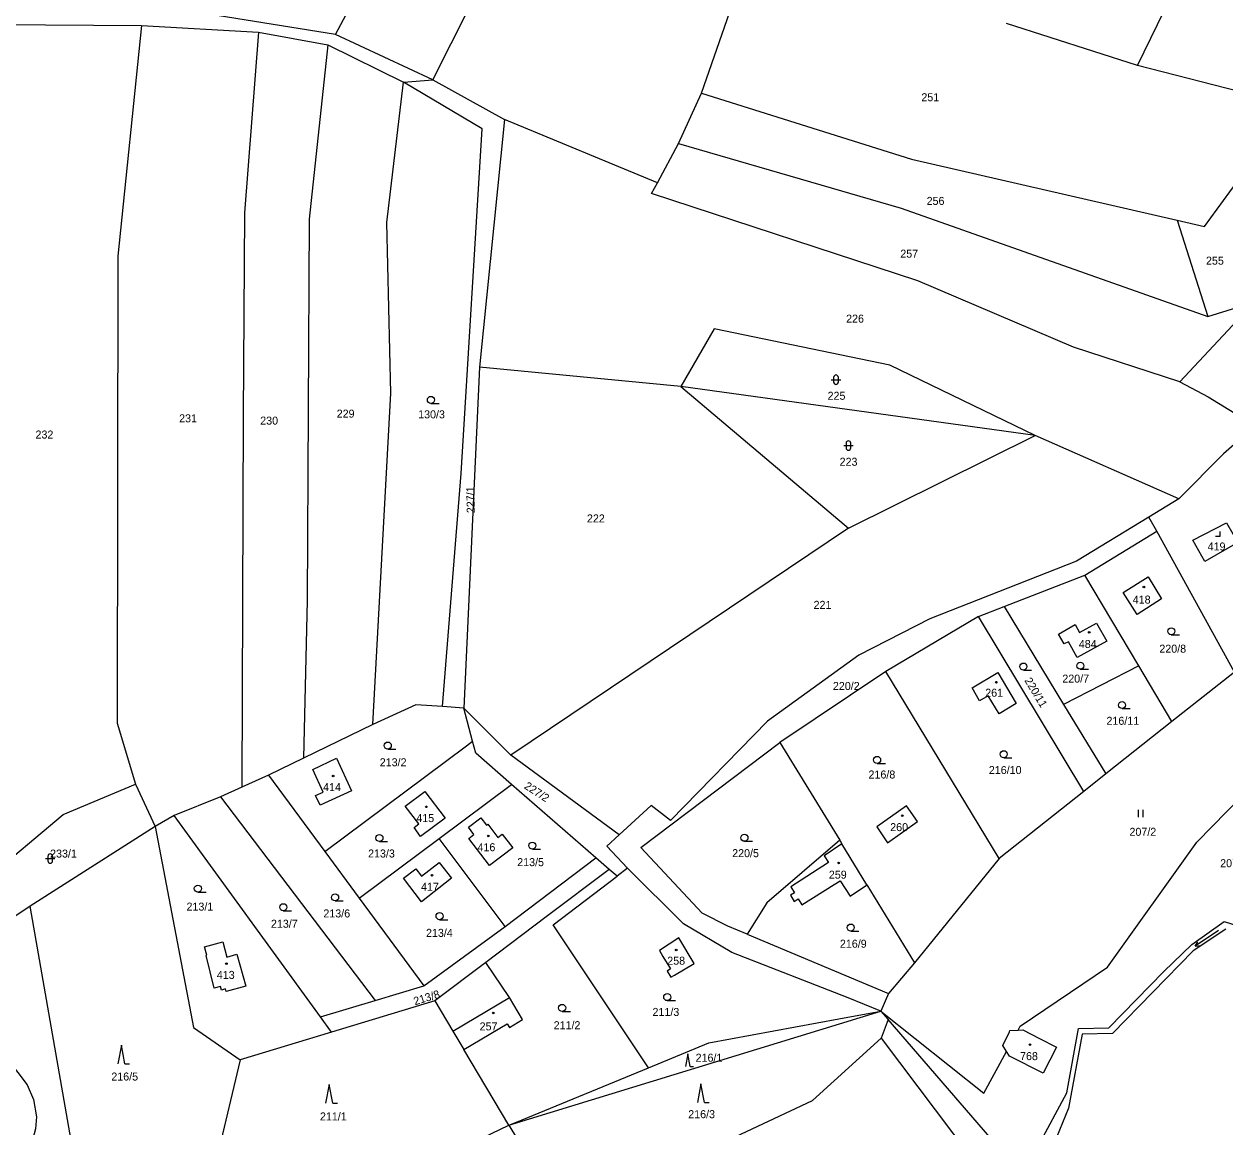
# Model space of a CAD drawing. Extents: x -725728 to -720881, y -1068679 to -1063504.
# Drawn here: x -722267.5 to -722012.3, y -1065928.4 to -1065694 of the extents above; entities that cross this region are included whole.
import ezdxf

# ---------------------------------------------------------------- set-up
doc = ezdxf.new("R2010")
doc.units = 0
for name, color, linetype in [('Hranice parcel', 7, 'Continuous'), ('Parcelní čísla', 7, 'Continuous'), ('Vnitřní kresba', 7, 'Continuous'), ('Značky budov', 7, 'Continuous'), ('Značky kultur', 7, 'Continuous')]:
    doc.layers.add(name, color=color, linetype=linetype)

# ---------------------------------------------------------------- blocks, each defined once
blk = doc.blocks.new('4.02_3')
at = {"layer": 'Značky budov'}
blk.add_circle((-0.001, 0), 0.0175, dxfattribs=at)
blk = doc.blocks.new('4.02_4')
at = {"layer": 'Značky budov'}
blk.add_circle((-0.001, 0), 0.0175, dxfattribs=at)
blk = doc.blocks.new('3.08_1')
at = {"layer": 'Značky kultur'}
for p, q in [((0, 0.4), (-0.075, 0)), ((0.075, 0), (0, 0.4)), ((0.075, 0), (0.175, 0))]:
    blk.add_line(p, q, dxfattribs=at)
blk = doc.blocks.new('3.04_2')
at = {"layer": 'Značky kultur'}
blk.add_line((0.001, 0), (0.176, 0), dxfattribs=at)
blk.add_circle((0.001, 0.075), 0.075, dxfattribs=at)
blk = doc.blocks.new('3.04_3')
at = {"layer": 'Značky kultur'}
blk.add_line((0.001, 0), (0.176, 0), dxfattribs=at)
blk.add_circle((0.001, 0.075), 0.075, dxfattribs=at)
blk = doc.blocks.new('3.06_1')
at = {"layer": 'Značky kultur'}
for p, q in [((-0.051, 0), (-0.051, 0.15)), ((0.049, 0), (0.049, 0.15))]:
    blk.add_line(p, q, dxfattribs=at)
blk = doc.blocks.new('3.16_2')
at = {"layer": 'Značky kultur'}
for p, q in [((-0.1, 0.1), (0.1, 0.1)), ((-0.05, 0.15), (-0.05, 0.05)), ((0.05, 0.05), (0.05, 0.15))]:
    blk.add_line(p, q, dxfattribs=at)
for centre, start, end in [((0, 0.15), 0, 180), ((0, 0.05), 180, 359.9879)]:
    blk.add_arc(centre, 0.05, start, end, dxfattribs=at)
blk = doc.blocks.new('3.08_3')
at = {"layer": 'Značky kultur'}
for p, q in [((0, 0.268), (-0.05, 0)), ((0.05, 0), (0, 0.268)), ((0.05, 0), (0.117, 0))]:
    blk.add_line(p, q, dxfattribs=at)
blk = doc.blocks.new('3.19_1')
at = {"layer": 'Značky kultur'}
for p, q in [((-0.1, 0), (0, 0)), ((0, 0), (0, 0.1))]:
    blk.add_line(p, q, dxfattribs=at)
blk = doc.blocks.new('8.02_47')
at = {"layer": 'Značky kultur'}
for p, q in [((0.247, 0.168), (-0.251, -0.168)), ((-0.251, -0.168), (-0.198, -0.072)), ((-0.251, -0.168), (-0.142, -0.155))]:
    blk.add_line(p, q, dxfattribs=at)

msp = doc.modelspace()

# ---------------------------------------------------------------- linework, layer by layer
at = {"layer": 'Hranice parcel'}
for p, q in [((-722123.52, -1065708.62), (-722111.98, -1065675.49)), ((-722274.03, -1065694.06), (-722242.52, -1065694.3)), ((-722242.52, -1065694.3), (-722217.66, -1065695.66)), ((-722201.3, -1065696.18), (-722228.16, -1065691.88)), ((-722030.85, -1065702.76), (-722058.7, -1065693.84)), ((-722217.66, -1065695.66), (-722202.89, -1065698.37)), ((-722180.56, -1065705.79), (-722201.3, -1065696.18)), ((-722202.89, -1065698.37), (-722186.82, -1065706.32)), ((-722000.7, -1065710.51), (-722030.85, -1065702.76)), ((-722186.82, -1065706.32), (-722180.56, -1065705.79)), ((-722180.56, -1065705.79), (-722165.35, -1065714.26)), ((-722128.38, -1065719.38), (-722123.52, -1065708.62)), ((-722165.35, -1065714.26), (-722170.64, -1065766.91)), ((-722132.88, -1065727.71), (-722165.35, -1065714.26)), ((-722132.88, -1065727.71), (-722128.38, -1065719.38)), ((-722022.43, -1065735.64), (-722015.94, -1065756.11)), ((-722005.99, -1065753.01), (-722021.85, -1065769.98)), ((-722015.94, -1065756.11), (-722005.99, -1065753.01)), ((-722170.64, -1065766.91), (-722174, -1065839.34)), ((-722127.91, -1065771.02), (-722170.64, -1065766.91)), ((-722127.91, -1065771.02), (-722092.23, -1065801.09)), ((-722052.63, -1065781.44), (-722127.91, -1065771.02)), ((-722092.23, -1065801.09), (-722052.63, -1065781.44)), ((-722022.04, -1065794.84), (-722052.63, -1065781.44)), ((-722022.04, -1065794.84), (-722028.42, -1065798.74)), ((-722026.74, -1065801.78), (-722028.42, -1065798.74)), ((-722092.23, -1065801.09), (-722163.99, -1065849.39)), ((-722042.06, -1065811.08), (-722026.74, -1065801.78)), ((-722010.26, -1065831.7), (-722026.74, -1065801.78)), ((-722059.2, -1065817.78), (-722042.06, -1065811.08)), ((-722030.6, -1065830.35), (-722042.06, -1065811.08)), ((-722064.66, -1065819.92), (-722059.2, -1065817.78)), ((-722059.2, -1065817.78), (-722046.55, -1065838.61)), ((-722064.66, -1065819.92), (-722084.3, -1065831.58)), ((-722042.28, -1065857.07), (-722064.66, -1065819.92)), ((-722084.3, -1065831.58), (-722106.82, -1065846.64)), ((-722060.25, -1065871.3), (-722084.3, -1065831.58)), ((-722030.6, -1065830.35), (-722046.55, -1065838.61)), ((-722023.54, -1065842.22), (-722030.6, -1065830.35)), ((-722010.26, -1065831.7), (-722023.54, -1065842.22)), ((-722174, -1065839.34), (-722178.54, -1065839.03)), ((-722163.99, -1065849.39), (-722174, -1065839.34)), ((-722172.14, -1065846.35), (-722174, -1065839.34)), ((-722046.55, -1065838.61), (-722037.6, -1065853.36)), ((-722023.54, -1065842.22), (-722037.6, -1065853.36)), ((-722193.33, -1065842.82), (-722208.06, -1065849.98)), ((-722106.82, -1065846.64), (-722094.13, -1065867.43)), ((-722208.06, -1065849.98), (-722215.54, -1065853.61)), ((-722140.98, -1065866.28), (-722163.99, -1065849.39)), ((-722215.54, -1065853.61), (-722221.2, -1065856.18)), ((-722215.54, -1065853.61), (-722203.56, -1065869.83)), ((-722037.6, -1065853.36), (-722042.28, -1065857.07)), ((-722243.74, -1065855.55), (-722239.6, -1065864.51)), ((-722221.2, -1065856.18), (-722225.69, -1065858.23)), ((-722179.25, -1065867.09), (-722163.85, -1065855.58)), ((-722145.97, -1065871.15), (-722163.85, -1065855.58)), ((-722042.28, -1065857.07), (-722060.25, -1065871.3)), ((-722225.69, -1065858.23), (-722235.53, -1065862.17)), ((-722225.69, -1065858.23), (-722192.83, -1065901.48)), ((-722235.53, -1065862.17), (-722239.6, -1065864.51)), ((-722204.49, -1065905), (-722235.53, -1065862.17)), ((-722239.6, -1065864.51), (-722266.17, -1065881.44)), ((-722196.22, -1065879.77), (-722179.25, -1065867.09)), ((-722165.24, -1065885.76), (-722179.25, -1065867.09)), ((-722094.13, -1065867.43), (-722093.65, -1065868.22)), ((-722203.56, -1065869.83), (-722196.22, -1065879.77)), ((-722088.34, -1065876.92), (-722093.65, -1065868.22)), ((-722165.24, -1065885.76), (-722145.97, -1065871.15)), ((-722143.11, -1065873.64), (-722145.97, -1065871.15)), ((-722060.25, -1065871.3), (-722078.24, -1065893.48)), ((-722141.44, -1065875.1), (-722143.11, -1065873.64)), ((-722139.21, -1065873.41), (-722141.44, -1065875.1)), ((-722088.34, -1065876.92), (-722078.24, -1065893.48)), ((-722196.22, -1065879.77), (-722182.5, -1065898.36)), ((-722266.17, -1065881.44), (-722275.86, -1065887.97)), ((-722254.23, -1065949.49), (-722266.17, -1065881.44)), ((-722182.5, -1065898.36), (-722165.24, -1065885.76)), ((-722113.79, -1065887.43), (-722083.74, -1065899.99)), ((-722169.35, -1065893.43), (-722180.13, -1065901.56)), ((-722078.24, -1065893.48), (-722083.74, -1065899.99)), ((-722192.83, -1065901.48), (-722182.5, -1065898.36)), ((-722083.74, -1065899.99), (-722085.4, -1065903.77)), ((-722204.49, -1065905), (-722192.83, -1065901.48)), ((-722180.13, -1065901.56), (-722202.14, -1065908.24)), ((-722202.14, -1065908.24), (-722204.49, -1065905)), ((-722164.41, -1065928.04), (-722085.4, -1065903.77)), ((-722085.4, -1065903.77), (-722083.83, -1065905.58)), ((-722083.83, -1065905.58), (-722085.32, -1065909.53)), ((-722202.14, -1065908.24), (-722221.54, -1065914.12)), ((-722164.41, -1065928.04), (-722173.99, -1065911.91)), ((-722221.54, -1065914.12), (-722229.33, -1065947.13)), ((-722164.41, -1065928.04), (-722152.51, -1065947.51))]:
    msp.add_line(p, q, dxfattribs=at)
for points in [[(-722201.3, -1065696.18), (-722138.26, -1065577.94), (-722128.23, -1065555.01)], [(-722030.85, -1065702.76), (-722019.46, -1065679.33), (-722013.77, -1065661.3), (-722007.43, -1065625.17), (-721992.31, -1065561.01)], [(-722180.56, -1065705.79), (-722145.45, -1065636.07), (-722132.28, -1065612.51), (-722126.14, -1065613.77)], [(-722242.52, -1065694.3), (-722247.56, -1065743.31), (-722247.66, -1065842.59), (-722243.74, -1065855.55)], [(-722217.66, -1065695.66), (-722220.61, -1065734.07), (-722220.91, -1065777.26), (-722221.2, -1065856.18)], [(-722202.89, -1065698.37), (-722206.9, -1065735.43), (-722207.31, -1065816.45), (-722208.06, -1065849.98)], [(-722193.33, -1065842.82), (-722189.51, -1065772.41), (-722190.37, -1065736.14), (-722186.82, -1065706.32)], [(-722178.54, -1065839.03), (-722174.54, -1065789.47), (-722170.09, -1065716.24), (-722186.82, -1065706.32)], [(-722123.52, -1065708.62), (-722078.88, -1065722.71), (-722022.43, -1065735.64)], [(-722128.38, -1065719.38), (-722081.09, -1065733.08), (-722015.94, -1065756.11)], [(-722021.85, -1065769.98), (-722044.45, -1065762.66), (-722077.5, -1065748.51), (-722134.09, -1065729.95), (-722132.88, -1065727.71)], [(-722022.43, -1065735.64), (-722016.59, -1065736.98), (-722009.86, -1065727.76)], [(-722052.63, -1065781.44), (-722083.49, -1065766.47), (-722120.8, -1065758.77), (-722127.91, -1065771.02)], [(-722021.85, -1065769.98), (-722015.81, -1065773.22), (-722005.78, -1065779.39)], [(-722005.78, -1065779.39), (-722012.57, -1065785.29), (-722022.04, -1065794.84)], [(-722028.42, -1065798.74), (-722043.84, -1065808.09), (-722074.97, -1065820.37), (-722090.06, -1065828.1), (-722109.45, -1065842.15), (-722130.11, -1065863.27), (-722134.2, -1065860.07), (-722140.98, -1065866.28)], [(-722011.91, -1065800), (-722009.56, -1065804.16), (-722016.51, -1065808.19), (-722019.12, -1065803.69), (-722011.91, -1065800)], [(-722028.58, -1065811.43), (-722025.77, -1065816.11), (-722030.94, -1065819.49), (-722033.9, -1065814.78), (-722028.58, -1065811.43)], [(-722047.65, -1065823.61), (-722044.09, -1065821.6), (-722043.15, -1065823.29), (-722039.53, -1065821.27), (-722037.38, -1065825.1), (-722043.65, -1065828.6), (-722045.53, -1065825.24), (-722046.47, -1065825.73), (-722047.65, -1065823.61)], [(-722065.95, -1065835.07), (-722060.55, -1065831.78), (-722056.61, -1065838.37), (-722060.28, -1065840.56), (-722062.57, -1065836.74), (-722064.43, -1065837.8), (-722065.95, -1065835.07)], [(-722056.22, -1065907.79), (-722055.76, -1065906.93), (-722037.21, -1065894.45), (-722018.27, -1065867.82), (-721983.08, -1065831.96)], [(-722051.89, -1065932.36), (-722045.84, -1065921.12), (-722043.4, -1065907.49), (-722036.92, -1065907.31), (-722025.26, -1065895.33), (-722019.33, -1065889.58), (-722012.43, -1065884.69), (-722008.21, -1065886.04), (-722000.63, -1065874.18), (-722000.39, -1065864.28), (-721990.8, -1065859.02), (-721988.48, -1065852.6), (-721979.8, -1065854.19), (-721975.47, -1065847.35), (-721974.71, -1065836.96)], [(-722178.54, -1065839.03), (-722184.22, -1065838.64), (-722193.33, -1065842.82)], [(-722203.56, -1065869.83), (-722173.41, -1065847.37), (-722172.14, -1065846.35)], [(-722163.85, -1065855.58), (-722171.44, -1065848.97), (-722172.14, -1065846.35)], [(-722113.79, -1065887.43), (-722117.88, -1065885.72), (-722123.37, -1065882.96), (-722136.41, -1065868.98), (-722106.82, -1065846.64)], [(-722201.06, -1065849.99), (-722197.89, -1065856.92), (-722204.53, -1065859.96), (-722205.51, -1065857.9), (-722203.92, -1065857.21), (-722206.09, -1065852.4), (-722201.06, -1065849.99)], [(-722275.73, -1065875.87), (-722259.12, -1065861.96), (-722243.74, -1065855.55)], [(-722183.6, -1065863.99), (-722186.44, -1065860.2), (-722182.26, -1065857.05), (-722177.98, -1065862.75), (-722183.18, -1065866.65), (-722184.54, -1065864.77), (-722183.6, -1065863.99)], [(-722077.59, -1065863.44), (-722079.94, -1065860.11), (-722086.27, -1065864.59), (-722084, -1065867.97), (-722077.59, -1065863.44)], [(-722165.83, -1065866.14), (-722163.6, -1065869.08), (-722168.55, -1065872.84), (-722172.92, -1065867.04), (-722171.85, -1065866.23), (-722173.04, -1065864.65), (-722170.39, -1065862.65), (-722169.2, -1065864.24), (-722168.93, -1065864.04), (-722166.8, -1065866.87), (-722165.83, -1065866.14)], [(-722239.6, -1065864.51), (-722231.48, -1065907.25), (-722221.54, -1065914.12)], [(-722140.98, -1065866.28), (-722143.59, -1065868.68), (-722139.21, -1065873.41)], [(-722094.13, -1065867.43), (-722109.6, -1065880.76), (-722113.79, -1065887.43)], [(-722093.65, -1065868.22), (-722097.41, -1065870.77), (-722096.52, -1065872.15), (-722104.55, -1065877.32), (-722103.77, -1065878.6), (-722104.6, -1065879.11), (-722103.79, -1065880.44), (-722102.96, -1065879.93), (-722102.2, -1065881.18), (-722095.34, -1065876.87), (-722094.03, -1065876.05), (-722091.94, -1065879.35), (-722088.46, -1065877), (-722088.34, -1065876.92)], [(-722176.62, -1065875.48), (-722183.01, -1065880.5), (-722186.82, -1065875.51), (-722184.23, -1065873.53), (-722182.99, -1065875.1), (-722179.24, -1065872.15), (-722176.62, -1065875.48)], [(-722143.11, -1065873.64), (-722156.49, -1065883.73), (-722169.35, -1065893.43)], [(-722134.78, -1065915.83), (-722155.02, -1065885.4), (-722141.44, -1065875.1)], [(-722085.4, -1065903.77), (-722092.32, -1065900.93), (-722117.02, -1065891.29), (-722127.31, -1065885.24), (-722139.21, -1065873.41)], [(-722131.74, -1065892.12), (-722130.06, -1065894.81), (-722130.78, -1065895.26), (-722129.99, -1065896.54), (-722129.27, -1065896.09), (-722125.09, -1065893.63), (-722128.29, -1065888.21), (-722132.42, -1065890.85), (-722131.74, -1065892.12)], [(-722012.1, -1065886.37), (-722019, -1065890.94), (-722036.15, -1065908.55), (-722042.6, -1065908.63), (-722045.52, -1065924.37), (-722049.37, -1065933.74)], [(-722222.21, -1065891.69), (-722220.33, -1065898.43), (-722224.49, -1065899.59), (-722224.64, -1065899.05), (-722225.51, -1065899.29), (-722225.72, -1065898.52), (-722227.02, -1065898.88), (-722228.79, -1065891.92), (-722228.6, -1065891.87), (-722229.09, -1065890.11), (-722225.24, -1065889.04), (-722224.33, -1065892.28), (-722222.21, -1065891.69)], [(-722173.99, -1065911.91), (-722164.77, -1065906.44), (-722164.31, -1065907.22), (-722161.51, -1065905.55), (-722164.3, -1065900.85), (-722169.35, -1065893.43)], [(-722180.13, -1065901.56), (-722176.32, -1065907.99), (-722173.99, -1065911.91)], [(-722285.72, -1065904.19), (-722273.03, -1065911.74), (-722270.78, -1065914.3), (-722268.77, -1065916.83), (-722266.77, -1065919.43), (-722265.43, -1065922.57), (-722264.84, -1065926.24), (-722265, -1065928.79), (-722265.96, -1065932.25), (-722268.18, -1065935.12), (-722272.65, -1065939.4)], [(-722134.78, -1065915.83), (-722121.96, -1065910.5), (-722094.31, -1065905.4), (-722085.4, -1065903.77)], [(-722085.4, -1065903.77), (-722063.49, -1065921.23), (-722058.68, -1065912.34)], [(-722057.74, -1065935.7), (-722060.85, -1065932.11), (-722083.83, -1065905.58)], [(-722058.68, -1065912.34), (-722059.47, -1065911.08), (-722058.08, -1065908.14), (-722057.95, -1065907.87), (-722056.22, -1065907.79)], [(-722056.22, -1065907.79), (-722055.23, -1065907.75), (-722051.7, -1065909.55), (-722048.03, -1065911.43), (-722050.87, -1065916.96), (-722058.05, -1065913.33), (-722058.68, -1065912.34)], [(-722152.51, -1065947.51), (-722099.94, -1065922.79), (-722085.32, -1065909.53)], [(-722085.32, -1065909.53), (-722066.07, -1065935.1), (-722076.78, -1065959.72), (-722108.09, -1065964.34), (-722132.88, -1065965.74), (-722139.03, -1065970.19)], [(-722164.41, -1065928.04), (-722161.59, -1065926.87), (-722134.78, -1065915.83)], [(-722229.33, -1065947.13), (-722179.01, -1065935.03), (-722164.41, -1065928.04)]]:
    msp.add_lwpolyline(points, dxfattribs=at)
at = {"layer": 'Vnitřní kresba'}
msp.add_line((-722176.32, -1065907.99), (-722164.3, -1065900.85), dxfattribs=at)

# ---------------------------------------------------------------- block references
at = {"layer": 'Značky budov', "xscale": 10, "yscale": 10}
for name, p in [('4.02_3', (-722029.49, -1065813.62)), ('4.02_3', (-722041.11, -1065823.24)), ('4.02_3', (-722060.83, -1065833.85)), ('4.02_3', (-722201.76, -1065853.78)), ('4.02_3', (-722181.96, -1065860.34)), ('4.02_3', (-722080.82, -1065862.22)), ('4.02_3', (-722168.79, -1065866.53)), ('4.02_3', (-722094.35, -1065872.28)), ('4.02_4', (-722180.74, -1065874.88)), ('4.02_3', (-722128.86, -1065890.77)), ('4.02_3', (-722224.44, -1065893.69)), ('4.02_4', (-722167.73, -1065904.16)), ('4.02_4', (-722053.67, -1065910.89))]:
    msp.add_blockref(name, p, dxfattribs=at)
at = {"layer": 'Značky kultur', "xscale": 10, "yscale": 10}
for name, p in [('3.16_2', (-722094.92, -1065770.55)), ('3.04_2', (-722181.01, -1065774.6)), ('3.16_2', (-722092.29, -1065784.56)), ('3.19_1', (-722013.3, -1065802.81)), ('3.04_2', (-722023.69, -1065823.78)), ('3.04_2', (-722043.02, -1065831.1)), ('3.04_2', (-722055.11, -1065831.27)), ('3.04_2', (-722034.14, -1065839.46)), ('3.04_2', (-722190.18, -1065848.07)), ('3.04_2', (-722086.19, -1065851.12)), ('3.04_3', (-722059.29, -1065849.91)), ('3.06_1', (-722030.15, -1065862.51)), ('3.04_2', (-722191.95, -1065867.72)), ('3.04_2', (-722159.44, -1065869.33)), ('3.04_3', (-722114.39, -1065867.67)), ('3.16_2', (-722261.89, -1065872.35)), ('3.04_2', (-722230.53, -1065878.47)), ('3.04_2', (-722201.37, -1065880.34)), ('3.04_3', (-722212.37, -1065882.43)), ('3.04_2', (-722179.17, -1065884.33)), ('3.04_2', (-722091.8, -1065886.75)), ('8.02_47', (-722016.08, -1065888.29)), ('3.04_2', (-722130.79, -1065901.54)), ('3.04_2', (-722153.12, -1065903.83)), ('3.08_1', (-722246.78, -1065914.97)), ('3.08_3', (-722126.38, -1065915.53)), ('3.08_1', (-722202.62, -1065923.34)), ('3.08_1', (-722123.62, -1065923.22))]:
    msp.add_blockref(name, p, dxfattribs=at)

# ---------------------------------------------------------------- texts
at = {"layer": 'Parcelní čísla'}
for s, p in [('251', (-722076.78, -1065710.36)), ('256', (-722075.66, -1065732.4)), ('257', (-722081.26, -1065743.61)), ('255', (-722016.3, -1065745.1)), ('226', (-722092.77, -1065757.42)), ('225', (-722096.71, -1065773.82)), ('229', (-722201.02, -1065777.62)), ('130/3', (-722183.71, -1065777.77)), ('231', (-722234.5, -1065778.61)), ('230', (-722217.27, -1065779.1)), ('232', (-722265.02, -1065782.06)), ('223', (-722094.15, -1065787.84)), ('222', (-722147.84, -1065799.89)), ('419', (-722015.95, -1065805.85)), ('221', (-722099.68, -1065818.26)), ('418', (-722031.86, -1065817.14)), ('484', (-722043.32, -1065826.58)), ('220/8', (-722026.21, -1065827.58)), ('220/7', (-722046.83, -1065833.94)), ('220/2', (-722095.58, -1065835.5)), ('261', (-722063.21, -1065836.94)), ('216/11', (-722037.45, -1065842.91)), ('213/2', (-722191.87, -1065851.72)), ('216/8', (-722088.01, -1065854.32)), ('216/10', (-722062.44, -1065853.37)), ('414', (-722203.91, -1065857)), ('415', (-722184.11, -1065863.59)), ('260', (-722083.4, -1065865.51)), ('207/2', (-722032.56, -1065866.5)), ('233/1', (-722261.92, -1065871.13)), ('213/3', (-722194.35, -1065871.11)), ('416', (-722171.1, -1065869.78)), ('220/5', (-722116.98, -1065871.04)), ('213/5', (-722162.66, -1065872.95)), ('207/5', (-722013.29, -1065873.18)), ('259', (-722096.44, -1065875.61)), ('417', (-722183.1, -1065878.18)), ('213/1', (-722232.93, -1065882.4)), ('213/6', (-722203.85, -1065883.85)), ('213/7', (-722214.99, -1065886.04)), ('213/4', (-722182.04, -1065887.98)), ('216/9', (-722094.09, -1065890.29)), ('258', (-722130.78, -1065893.9)), ('413', (-722226.49, -1065896.92)), ('211/3', (-722133.91, -1065904.79)), ('257', (-722170.65, -1065907.86)), ('211/2', (-722154.92, -1065907.61)), ('216/1', (-722124.75, -1065914.52)), ('768', (-722055.81, -1065914.18)), ('216/5', (-722248.91, -1065918.52)), ('211/1', (-722204.58, -1065927)), ('216/3', (-722126.32, -1065926.52))]:
    msp.add_text(s, height=1.7, dxfattribs=at).set_placement(p)
for s, rotation, p in [('227/1', 91, (-722171.68, -1065797.91)), ('220/11', 301, (-722054.94, -1065833.48)), ('227/2', 327, (-722161.33, -1065856.32)), ('213/8', 17, (-722184.39, -1065902.53))]:
    msp.add_text(s, height=1.7, rotation=rotation, dxfattribs=at).set_placement(p)

doc.saveas('drawing.dxf')
